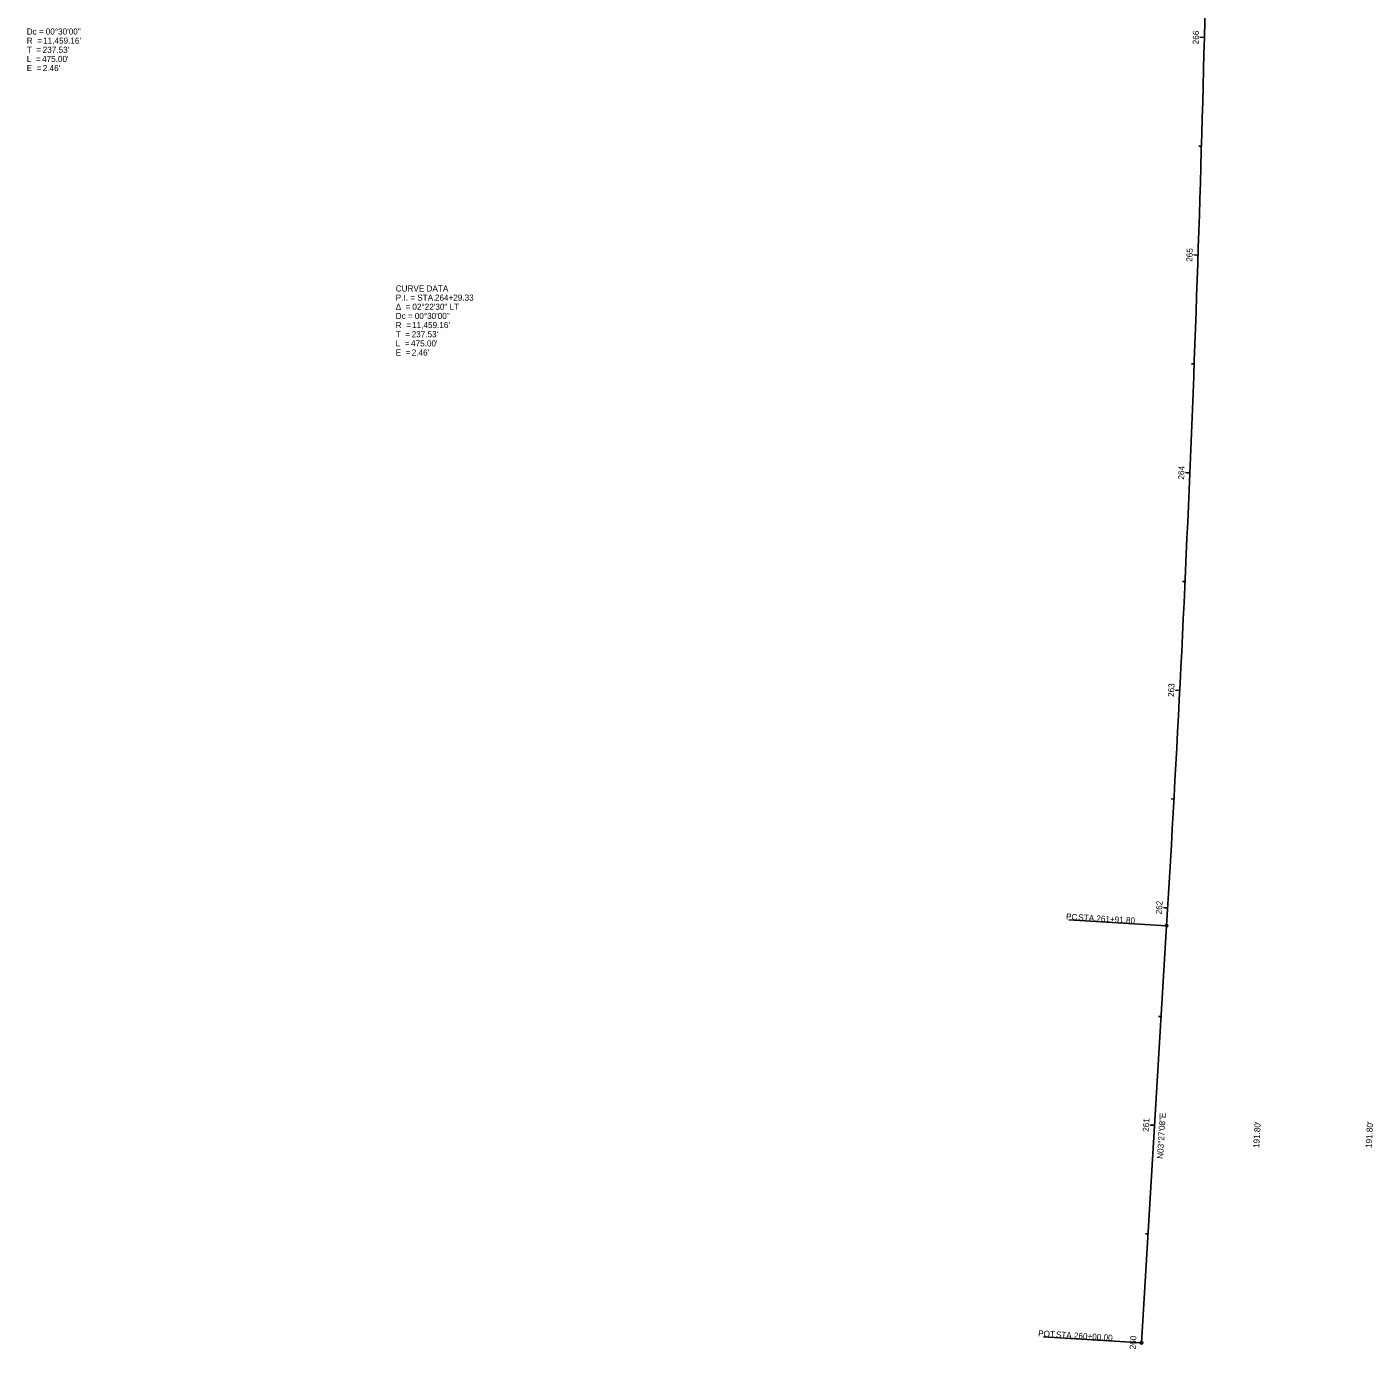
# Model space of a CAD drawing. Extents: x 1505540 to 1506187, y 327390 to 328596.
# Drawn here: x 1505540 to 1506158, y 327390 to 327997 of the extents above; entities that cross this region are included whole.
import ezdxf

# ---------------------------------------------------------------- set-up
doc = ezdxf.new("R2010")
doc.units = 0
for name, color, linetype in [('GE_X_Alignment', 7, 'Continuous'), ('GE_X_Alignment_100_Bearings', 7, 'Continuous'), ('GE_X_Alignment_100_Cardinal_Points', 7, 'Continuous'), ('GE_X_Alignment_100_Curve_Data', 7, 'Continuous'), ('GE_X_Alignment_100_Distances', 7, 'Continuous'), ('GE_X_Alignment_100_Stations', 7, 'Continuous'), ('GE_X_Alignment_500_Bearings', 7, 'Continuous'), ('GE_X_Alignment_500_Cardinal_Points', 7, 'Continuous'), ('GE_X_Alignment_500_Curve_Data', 7, 'Continuous'), ('GE_X_Alignment_500_Distances', 7, 'Continuous'), ('GE_X_Alignment_500_Stations', 7, 'Continuous')]:
    doc.layers.add(name, color=color, linetype=linetype)

msp = doc.modelspace()

# ---------------------------------------------------------------- linework, layer by layer
at = {"layer": 'GE_X_Alignment'}
msp.add_line((1506051.31, 327393.31), (1506062.86, 327584.77), dxfattribs=at)
msp.add_arc((1494624.5, 328274.78), 11459.16, 356.547823, 358.922822, dxfattribs=at)
at = {"layer": 'GE_X_Alignment_100_Cardinal_Points'}
for p, q in [((1506062.86, 327584.77), (1506017.94, 327587.48)), ((1506051.31, 327393.31), (1506006.39, 327396.02))]:
    msp.add_line(p, q, dxfattribs=at)
for centre in [(1506062.86, 327584.77), (1506051.31, 327393.31)]:
    msp.add_circle(centre, 0.6, dxfattribs=at)
at = {"layer": 'GE_X_Alignment_100_Stations'}
for p, q in [((1506080.18, 327992.58), (1506078.18, 327992.63)), ((1506078.84, 327942.59), (1506077.64, 327942.63)), ((1506077.28, 327892.62), (1506075.28, 327892.69)), ((1506075.51, 327842.65), (1506074.31, 327842.7)), ((1506073.51, 327792.69), (1506071.51, 327792.77)), ((1506071.3, 327742.74), (1506070.1, 327742.8)), ((1506068.87, 327692.8), (1506066.87, 327692.9)), ((1506066.22, 327642.87), (1506065.02, 327642.94)), ((1506063.35, 327592.95), (1506061.36, 327593.07)), ((1506060.35, 327543.04), (1506059.15, 327543.11)), ((1506057.33, 327493.13), (1506055.34, 327493.25)), ((1506054.32, 327443.22), (1506053.13, 327443.3)), ((1506051.31, 327393.31), (1506049.32, 327393.43))]:
    msp.add_line(p, q, dxfattribs=at)
at = {"layer": 'GE_X_Alignment_500_Cardinal_Points'}
for p, q in [((1506062.86, 327584.77), (1506017.94, 327587.48)), ((1506051.31, 327393.31), (1506006.39, 327396.02))]:
    msp.add_line(p, q, dxfattribs=at)
for centre in [(1506062.86, 327584.77), (1506051.31, 327393.31)]:
    msp.add_circle(centre, 0.6, dxfattribs=at)
at = {"layer": 'GE_X_Alignment_500_Stations'}
for p, q in [((1506080.18, 327992.58), (1506078.98, 327992.61)), ((1506077.28, 327892.62), (1506075.28, 327892.69)), ((1506073.51, 327792.69), (1506072.31, 327792.74)), ((1506068.87, 327692.8), (1506067.67, 327692.86)), ((1506063.35, 327592.95), (1506062.16, 327593.02)), ((1506057.33, 327493.13), (1506056.14, 327493.2)), ((1506051.31, 327393.31), (1506049.32, 327393.43))]:
    msp.add_line(p, q, dxfattribs=at)

# ---------------------------------------------------------------- texts
at = {"layer": 'GE_X_Alignment_100_Bearings'}
msp.add_text('N03°27\'08"E', height=2.8, rotation=86.54782, dxfattribs=at).set_placement((1506061.21, 327477.65))
at = {"layer": 'GE_X_Alignment_100_Cardinal_Points'}
for s, p in [('PC', (1506016.61, 327587.59)), (' STA. ', (1506021.2, 327587.32)), ('261+91.80', (1506030.51, 327586.75)), ('POT', (1506003.8, 327396.22)), (' STA. ', (1506010.92, 327395.79)), ('260+00.00', (1506020.22, 327395.23))]:
    msp.add_text(s, height=2.8, rotation=356.54782, dxfattribs=at).set_placement(p)
at = {"layer": 'GE_X_Alignment_100_Curve_Data'}
for s, p in [('CURVE DATA', (1505708.89, 327875.9)), ('P.I. = STA. ', (1505708.89, 327871.7)), ('264+29.33', (1505726.88, 327871.7)), ('Δ  = ', (1505708.89, 327867.5)), ('02°22\'30" LT', (1505716.53, 327867.5)), ('Dc = ', (1505708.89, 327863.3)), ('R  = ', (1505708.89, 327859.1)), ("11,459.16'", (1505716.42, 327859.1)), ('00°30\'00"', (1505717.63, 327863.3)), ('T  = ', (1505708.89, 327854.9)), ("237.53'", (1505716.21, 327854.9)), ('L  = ', (1505708.89, 327850.7)), ('E  = ', (1505708.89, 327846.5)), ("475.00'", (1505715.92, 327850.7)), ("2.46'", (1505716.23, 327846.5))]:
    msp.add_text(s, height=2.8, dxfattribs=at).set_placement(p)
at = {"layer": 'GE_X_Alignment_100_Distances'}
msp.add_text("191.80'", height=2.8, rotation=86.54782, dxfattribs=at).set_placement((1506105.35, 327482.62))
at = {"layer": 'GE_X_Alignment_100_Stations'}
for s, rotation, p in [('266', 88.58882, (1506077.6, 327989.38)), ('265', 88.08882, (1506074.68, 327889.5)), ('264', 87.58882, (1506070.87, 327789.52)), ('263', 87.08882, (1506066.21, 327689.73)), ('262', 86.58882, (1506060.67, 327589.89)), ('261', 86.54782, (1506054.65, 327490.07)), ('260', 86.54782, (1506048.62, 327390.2))]:
    msp.add_text(s, height=2.8, rotation=rotation, dxfattribs=at).set_placement(p)
at = {"layer": 'GE_X_Alignment_500_Bearings'}
msp.add_text('N03°27\'08"E', height=2.8, rotation=86.54782, dxfattribs=at).set_placement((1506061.21, 327477.65))
at = {"layer": 'GE_X_Alignment_500_Cardinal_Points'}
for s, p in [('PC', (1506016.61, 327587.59)), (' STA. ', (1506021.2, 327587.32)), ('261+91.80', (1506030.51, 327586.75)), ('POT', (1506003.8, 327396.22)), (' STA. ', (1506010.92, 327395.79)), ('260+00.00', (1506020.22, 327395.23))]:
    msp.add_text(s, height=2.8, rotation=356.54782, dxfattribs=at).set_placement(p)
at = {"layer": 'GE_X_Alignment_500_Curve_Data'}
for s, p in [('Dc = ', (1505539.46, 327993.88)), ('R  = ', (1505539.46, 327989.68)), ("11,459.16'", (1505546.99, 327989.68)), ('00°30\'00"', (1505548.2, 327993.88)), ('T  = ', (1505539.46, 327985.48)), ("237.53'", (1505546.78, 327985.48)), ('L  = ', (1505539.46, 327981.28)), ('E  = ', (1505539.46, 327977.08)), ("475.00'", (1505546.49, 327981.28)), ("2.46'", (1505546.8, 327977.08))]:
    msp.add_text(s, height=2.8, dxfattribs=at).set_placement(p)
at = {"layer": 'GE_X_Alignment_500_Distances'}
msp.add_text("191.80'", height=2.8, rotation=86.54782, dxfattribs=at).set_placement((1506156.97, 327482.62))
at = {"layer": 'GE_X_Alignment_500_Stations'}
for s, rotation, p in [('265', 88.08882, (1506074.68, 327889.5)), ('260', 86.54782, (1506048.62, 327390.2))]:
    msp.add_text(s, height=2.8, rotation=rotation, dxfattribs=at).set_placement(p)

doc.saveas('drawing.dxf')
